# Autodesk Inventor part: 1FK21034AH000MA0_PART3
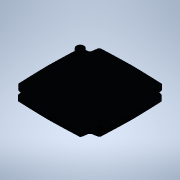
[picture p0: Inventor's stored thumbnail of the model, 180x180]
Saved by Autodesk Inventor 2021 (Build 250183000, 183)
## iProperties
Created: 2025-04
Part Number: 1FK21034AH000MA0_PART3
Material: Generic
Catalog Web Link: www.3dfindit.com
Description: -Servo synchronous motor
Document SubType Name: Modeling
Designer: psAdmin
Mass: 11.8521 g
Surface Area: 76.041 cm^2
Volume: 11.8521 cm^3
Density: 1 g/cm^3
Appearance: PSOLRGB-38-46-56
Category: PARTsolutions
Title: 1FK21034AH000MA0_PART3
Author: Cadenas PARTsolutions
Comments: Servo synchronous motor
Sending System: PARTsolutions
Preprocessor: ST-DEVELOPER v19.3
PSOL_IDENT_0: {$CADENAS_DATA/23d-libs/siemens_ag/_cat_/ec/b7/1fk21034ah000ma0.prj},213 {VTYP=3D},{NB=1FK21034AH000
PSOL_IDENT_1: MA0_PART3},{LINA=1FK21034AH000MA0_PART3},{NN=1FK21034AH000MA0_PART3},{NOPRJ=TRUE},{DATE=19.08.2025 1
PSOL_IDENT_2: 4:01:05},{GEOMDATE=30.07.2025 02:01:02},{VERSION=},{LINEID=10},{WBVAR=},{WBNUMERIC=}  {NB=1FK21034AH
PSOL_IDENT_3: 000MA0_PART3},{LINA=1FK21034AH000MA0_PART3},{KT=DUMMY},{PREVIEW=../../../_pool_/7c/50/p_d211_xx_0093
PSOL_IDENT_4: 2j.png},{DESCSHORT=SIMOTICS S-1FK2 HD, SINAMICS S210 3AC 400V-480V, 1.01 Nm, 4500 rpm},{DESCLONG=SIM
PSOL_IDENT_5: OTICS S-1FK2 HD servo motor M0=1.27 Nm; PN = 0.48 kW at nN=4500 rpm (380-480 V); PN = 0.3 kW at nN=2
PSOL_IDENT_6: 500 rpm (200-240 V); degree of protection IP64; cylindrical shaft D14 x 30 mm; absolute encoder 22-b
PSOL_IDENT_7: it + 12-bit multiturn (encoder AM22DQC); with OCC interface; plug size M17, rotatable; SIMOTICS S-1F
PSOL_IDENT_8: K2 servomotorfor a wide range of uses in industrial environments. SIMOTICS S‑1FK2 servomotors are co
PSOL_IDENT_9: mpact synchronous motors with a high dynamic performance that set themselves apart as a result of th
PSOL_IDENT_10: eir high power density, degree of protection and overload capability. The motors are available in tw
PSOL_IDENT_11: o variants: as High Dynamic variant (highest dynamic performance as a result of the low intrinsic mo
PSOL_IDENT_12: ment of inertia for applications demanding a high dynamic performance with low moved masses) - and a
PSOL_IDENT_13: s Compact variant (precise and stable closed-loop control for medium up to large moved masses as a r
PSOL_IDENT_14: esult of a medium intrinsic moment of inertia). SIMOTICSS‑1FK2 servomotors fully exploit their stren
PSOL_IDENT_15: gths in a system with the SINAMICSS210 frequency converter and simple connection using the one cable
PSOL_IDENT_16: connection (OCC). Advantages include the short control and positioning times, fast and precise corr
PSOL_IDENT_17: ection of disturbing quantities as well as stable control with a high dynamic performance. The servo
PSOL_IDENT_18: motors can be configured to address a wide range of requirements. For example with and without hold
PSOL_IDENT_19: ing brake, IP64 or IP65 degree of protection, singleturn or multiturn absolute encoders - to name ju
PSOL_IDENT_20: st a few. Further, the servomotors are available in different shaft heights extending from 20 to 100
PSOL_IDENT_21: . A shaft sealing ring is available to achieve an IP65 degree of protection and for subsequent mount
PSOL_IDENT_22: ing at the motor or as spare part. SIMOTICS - the optimum motor for each and every motion control ap
PSOL_IDENT_23: plication.},{INTNO=4034106444822},{SUPPLIERALTNO=1FK2103-4AH00-0MA0},{MANUID=1FK21034AH000MA0},{MANU
PSOL_IDENT_24: NAME=Siemens},{MANUTYPEDESC=SYNCHRONOUS MOTOR 1FK2 HD 1,27 NM},{AAU732=SIMOTICS},{AAO057=S-1FK2},{AA
PSOL_IDENT_25: U734=SIMOTICS S-1FK2 HD servo motor M0=1.27 Nm; PN = 0.48 kW at nN=4500 rpm (380-480 V); PN = 0.3 kW
PSOL_IDENT_26: at nN=2500 rpm (200-240 V); degree of protection IP64; cylindrical shaft D14 x 30 mm; absolute enco
PSOL_IDENT_27: der 22-bit + 12-bit multiturn (encoder AM22DQC); with OCC interface; plug size M17, rotatable;},{AAW
PSOL_IDENT_28: 338=SYNCHRONOUS MOTOR 1FK2 HD 1,27 NM},{AAO742=SIMOTICS},{AAO663=4034106444822},{NOCUPEROU=1},{PRICE
PSOL_IDENT_29: QUANTITY=1},{QUANTITYMIN=1},{QUANTITYINT=1},{CTN=85015100},{COO=RO},{AAO676=1FK2103-4AH00-0MA0},{AAO
PSOL_IDENT_30: 677=Siemens AG},{ORDERUNIT=C62},{CONTENTUNIT=C62}
NB: 1FK21034AH000MA0_PART3
NT: Servo synchronous motor
NBSYN: $MANUID._PART3
LINA: 1FK21034AH000MA0_PART3
CATALOG: SIEMENS
PREVIEW: ../../../_pool_/7c/50/p_d211_xx_00932j.png
DESCSHORT: SIMOTICS S-1FK2 HD, SINAMICS S210 3AC 400V-480V, 1.01 Nm, 4500 rpm
DESCLONG: SIMOTICS S-1FK2 HD servo motor M0=1.27 Nm; PN = 0.48 kW at nN=4500 rpm (380-480 V); PN = 0.3 kW at nN=2500 rpm (200-240 V); degree of protection IP64; cylindric
INTNO: 4034106444822
SUPPLIERALTNO: 1FK2103-4AH00-0MA0
MANUID: 1FK21034AH000MA0
MANUNAME: Siemens
MANUTYPEDESC: SYNCHRONOUS MOTOR 1FK2 HD 1,27 NM
AAU732: SIMOTICS
AAO057: S-1FK2
AAU734: SIMOTICS S-1FK2 HD servo motor M0=1.27 Nm; PN = 0.48 kW at nN=4500 rpm (380-480 V); PN = 0.3 kW at nN=2500 rpm (200-240 V); degree of protection IP64; cylindric
AAW338: SYNCHRONOUS MOTOR 1FK2 HD 1,27 NM
AAO742: SIMOTICS
AAO663: 4034106444822.0
NOCUPEROU: 1
PRICEQUANTITY: 1
QUANTITYMIN: 1
QUANTITYINT: 1
CTN: 85015100
COO: RO
ARTICLENO: 1FK21034AH000MA0_PART3
BOMINFO: 1FK21034AH000MA0_PART3
CREATOR: CADENAS GmbH
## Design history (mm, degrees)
feature "2025_04_17_15_01_37_0189"
body "Solid1"
